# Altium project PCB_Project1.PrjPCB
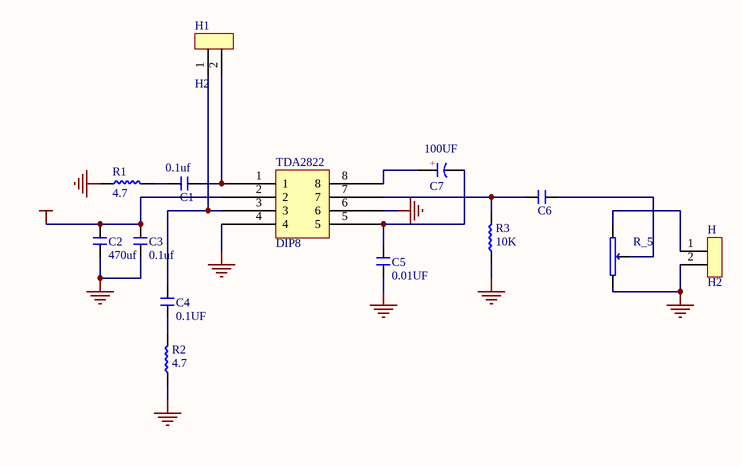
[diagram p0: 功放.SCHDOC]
1 sheet, 14 parts. Net scope: global (net labels, ports and power ports of the same name join across sheets).
Board file: PCB1.PcbDoc

## Sheet 功放.SCHDOC
size A4

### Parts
C1  value 0.1uf  [C2]  (hidden comment: CC1)
C2  value 470uf  [C2]  (hidden comment: CC1)
C3  value 0.1uf  [C2]  (hidden comment: CC1)
C4  value 0.1UF  [C2]  (hidden comment: CC1)
C5  value 0.01UF  [C2]  (hidden comment: CC1)
C6  CC1  [C2]  (value not drawn)
C7  CC2  [CC1+]  (value not drawn)
H  H2  [H2]
H1  H2  [H2]
R1  value 4.7  [RR2]  (hidden comment: R_4)
R2  value 4.7  [RR2]  (hidden comment: R_4)
R3  value 10K  [RR2]  (hidden comment: R_4)
R_5  R_DB2  [RD_B]  (value not drawn)
TDA2822  DIP8  [DIP8]

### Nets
GND: C2.1 C3.1 C5.1 H.2 R1.1 R2.1 R3.1 R_5.3 TDA2822.4 TDA2822.6
VCC: C2.2 C3.2 TDA2822.2
NetC1_1: C1.1 R1.2
NetC1_2: C1.2 H1.2 TDA2822.1
NetC4_1: C4.1 R2.2
NetC4_2: C4.2 H1.1 TDA2822.3
NetC5_2: C5.2 C7.2 TDA2822.5
NetC6_1: C6.1 R3.2 TDA2822.7
NetC6_2: C6.2 R_5.2
NetC7_1: C7.1 TDA2822.8
NetH_1: H.1 R_5.1

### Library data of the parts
C1-C5 = CC1: 电容
C6 = CC1: 电容; value: 100uf
C7 = CC2: 电解电容
R1-R3 = RR2
R_5 = R_DB2: VALUE: 1K
TDA2822 = DIP8: оƬ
